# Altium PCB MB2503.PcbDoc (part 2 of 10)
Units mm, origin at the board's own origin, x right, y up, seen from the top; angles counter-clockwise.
Board outline 127 x 97 mm, 6 copper layers (Top Layer, Signal Layer 1, Signal Layer 2, Signal Layer 3, Signal Layer 4, Bottom Layer), stack 1.557 mm thick; 572 components, 468 nets, 2377 pads, 1704 vias.
Unrouted connection lines stored in the file: 3.
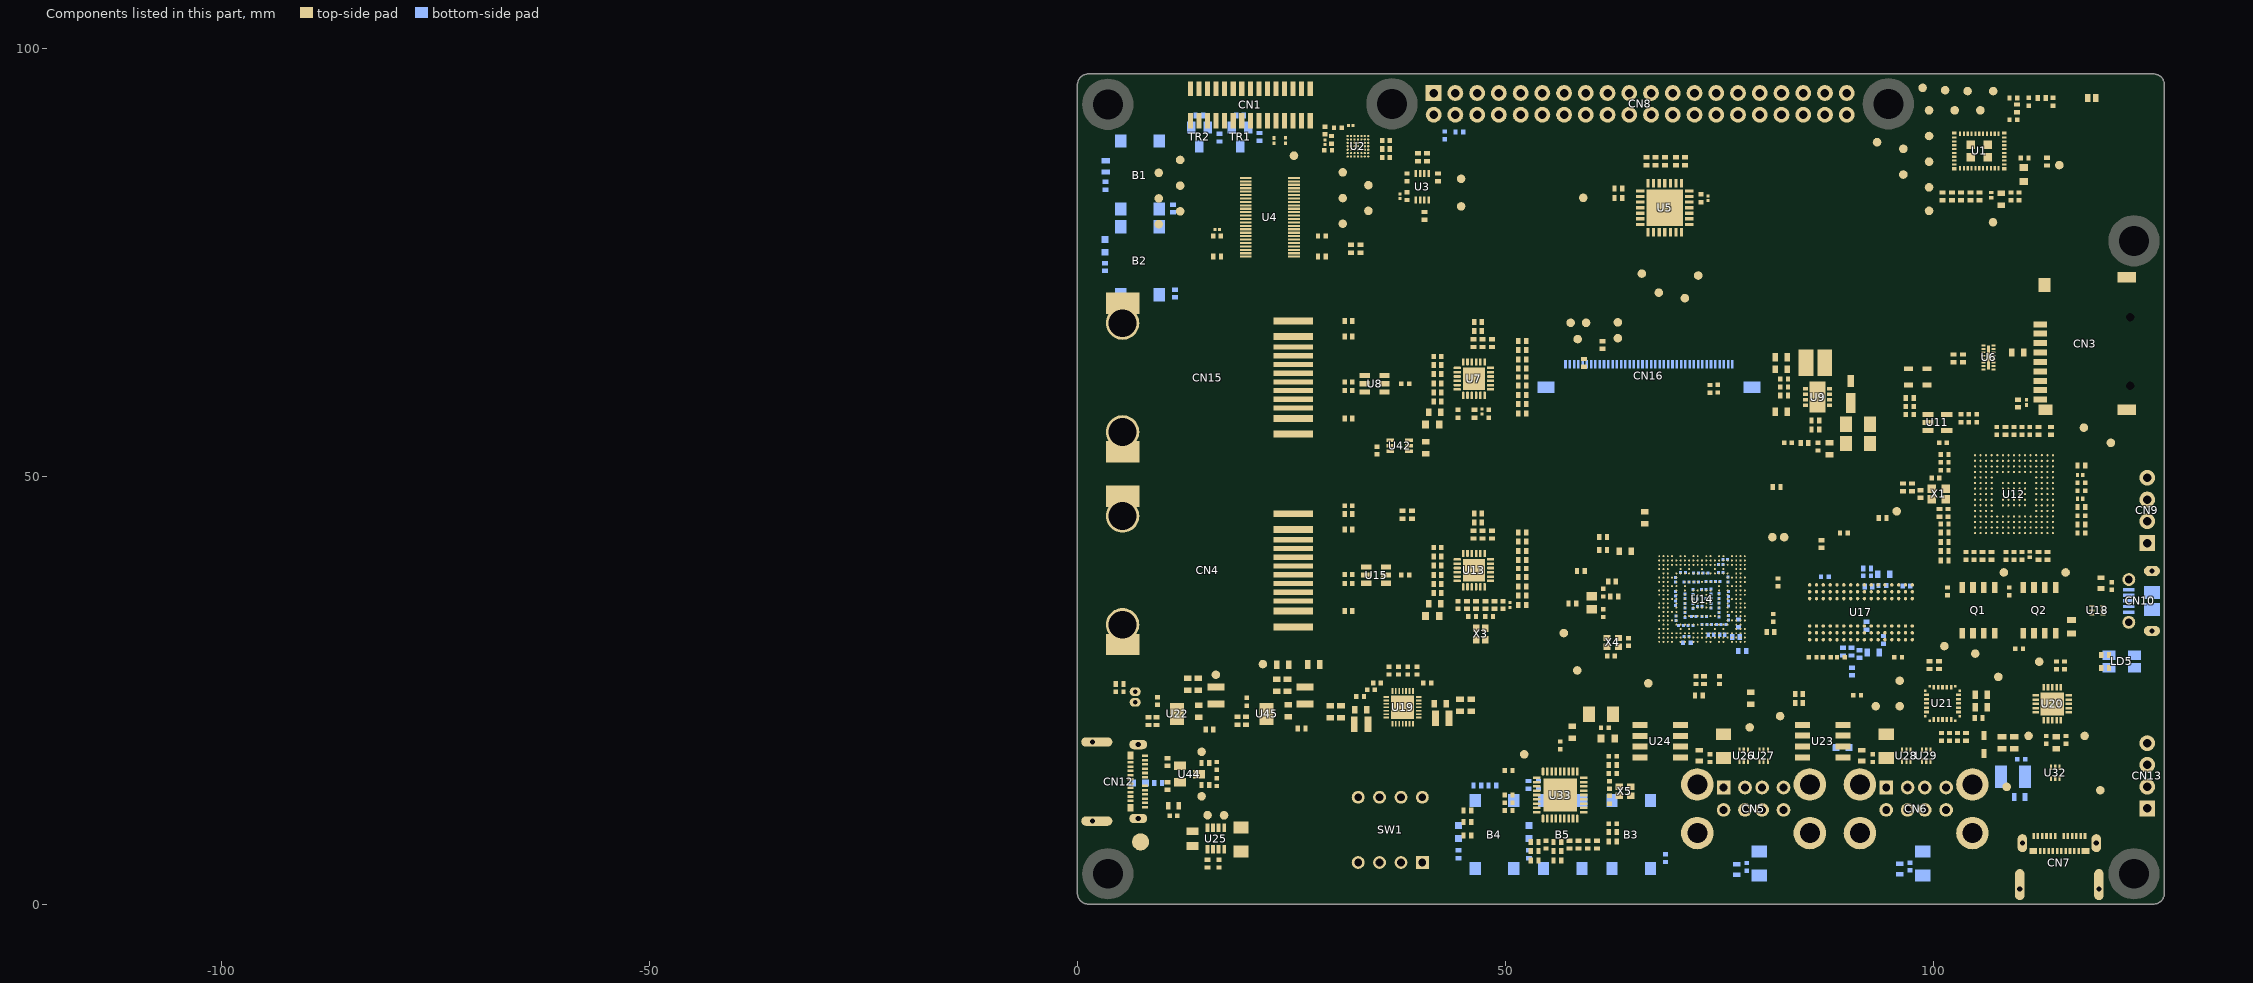
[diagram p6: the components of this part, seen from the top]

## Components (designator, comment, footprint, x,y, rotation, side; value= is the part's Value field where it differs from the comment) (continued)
TP32 "Test Point" TP_SMD_1MM#1 9.5,79.45 r90 top value=N/A
TP33 "Test Point" TP_SMD_1MM#1 72.525,73.45 r90 top value=N/A
TP34 "Test Point" TP_SMD_1MM#1 65.95,73.675 r90 top value=N/A
TP35 "Test Point" TP_SMD_1MM#1 70.975,70.8 r90 top value=N/A
TP36 "Test Point" TP_SMD_1MM#1 67.925,71.45 r90 top value=N/A
TP37 "Test Point" TP_SMD_1MM#1 59.425,67.925 r90 top value=N/A
TP38 "Test Point" TP_SMD_1MM#1 117.6,55.675 r180 top value=N/A
TP39 "Test Point" TP_SMD_1MM#1 120.75,53.9 r180 top value=N/A
TP40 "Test Point" TP_SMD_1MM#1 58.45,66.025 r90 top value=N/A
TP41 "Test Point" TP_SMD_1MM#1 63.145,66.125 r90 top value=N/A
TP42 "Test Point" TP_SMD_1MM#1 57.625,67.925 r90 top value=N/A
TP43 "Test Point" TP_SMD_1MM#1 63.145,67.975 r180 top value=N/A
TP44 "Test Point" TP_SMD_1MM#1 95.725,45.9 r270 top value=N/A
TP45 "Test Point" TP_SMD_1MM#2 81.25,42.875 r0 top value=N/A
TP46 "Test Point" TP_SMD_1MM#3 82.575,42.825 r0 top value=N/A
TP47 "Test Point" TP_SMD_1MM#1 108.25,38.75 r180 top value=N/A
TP48 "Test Point" TP_SMD_1MM#1 115.45,38.75 r180 top value=N/A
TP49 "Test Point" TP_SMD_1MM#1 21.675,28.05 r90 top value=N/A
TP50 "Test Point" TP_SMD_1MM#1 56.825,31.675 r90 top value=N/A
TP51 "Test Point" TP_SMD_1MM#1 101.3,30.15 r180 top value=N/A
TP52 "Test Point" TP_SMD_1MM#1 104.9,29.275 r180 top value=N/A
TP53 "Test Point" TP_SMD_1MM#1 112.375,28.325 r180 top value=N/A
TP54 "Test Point" TP_SMD_1MM#1 58.4,27.3 r90 top value=N/A
TP55 "Test Point" TP_SMD_1MM#1 107.6,26.55 r180 top value=N/A
TP56 "Test Point" TP_SMD_1MM#1 96.075,26.1 r180 top value=N/A
TP57 "Test Point" TP_SMD_1MM#1 66.7,25.8 r90 top value=N/A
TP58 "Test Point" TP_SMD_1MM#4 93.275,23.1 r180 top value=N/A
TP59 "Test Point" TP_SMD_1MM#1 96.075,23.125 r180 top value=N/A
TP61 "Test Point" TP_SMD_1MM#1 82.1,21.975 r90 top value=N/A
TP62 "Test Point" TP_SMD_1MM#1 16.175,26.8 r90 top value=N/A
TP63 "Test Point" TP_SMD_1MM#1 78.55,20.65 r180 top value=N/A
TP64 "Test Point" TP_SMD_1MM#1 111.125,19.65 r270 top value=N/A
TP65 "Test Point" TP_SMD_1MM#1 117.675,19.65 r270 top value=N/A
TP67 "Test Point" TP_SMD_1MM#1 17.125,10.375 r90 top value=N/A
TP68 "Test Point" TP_SMD_1MM#1 15.2,10.4 r180 top value=N/A
TP73 "Test Point" TP_SMD_1MM#1 14.5,12.6 r270 top value=N/A
TP74 "Test Point" TP_SMD_1MM#1 108.575,13.7 r180 top value=N/A
TP75 "Test Point" TP_SMD_1MM#1 119.511,13.303 r180 top value=N/A
TP76 "Test Point" TP_SMD_2MM 7.375,7.275 r180 top value=N/A
TP77 "Test Point" TP_SMD_1MM#1 14.5,17.8 r180 top value=N/A
TR1 "BSN20" MOS_SOT23 19,89.65 r0 bottom value=FDV301N
TR2 "BSN20" MOS_SOT23 14.25,89.65 r0 bottom value=FDV301N
U1 "LBEE5KL1DX-883" MOD_WLAN-BT_MURATA_LBEE5KL1DX-883 105.375,88 r180 top value=LBEE5KL1DX-977
U2 "STMIPID02" ICC_VFBGA49_3X3_P040 32.775,88.55 r270 top value=STMIPID02/TR
U3 "SN74LVC2T45DCUT" ICC_VSSOP8_DCU_R-PDSO-G8_2X2P30_P050 40.29,83.815 r0 top
U4 "SN74AVC16T245DGVR" ICC_TVSOP48_9P8X6P6_P040 22.475,80.25 r270 top
U5 "MCP23017" ICC_QFN28-EPAD_6X6_P065 68.625,81.375 r90 top value=MCP23017T-E/ML
U6 "EMIF06-MSD02N16" ESD_UQFN16L-EPAD_3P5X1P2_P040 106.45,63.875 r270 top
U7 "LAN8742A-CZ-TR" ICC_VQFN24-EPAD_4X4_P050 46.325,61.4 r90 top
U8 "USBLC6-4SC6" ESD_SOT23-6L 34.725,60.8 r270 top
U9 "STLD40DPUR" ICC_QFN8-EPAD_3X3_P065 86.475,59.25 r270 top
U10 "ESD-TRANSIL" ESD_ST0201 110.875,58.625 r270 top value=ESDALC6V1-1U2
U11 "LD3985M33R" REG_SOT23-5L 100.475,56.275 r270 top
U12 "ST-LINKV3E" ICC_UFBGA201_176+25_10X10_P065 109.425,47.9 r0 top value=STM32F723IEK6
U13 "LAN8742A-CZ-TR" ICC_VQFN24-EPAD_4X4_P050 46.325,39.025 r90 top
U14 "STM32MP135FAF7" ICC_TFBGA320_11X11_STM32MP135FA7_P050_H1P20 72.975,35.65 r0 top locked
U15 "USBLC6-4SC6" ESD_SOT23-6L 34.9,38.45 r270 top
U16 "ESD-TRANSIL" ESD_QFN2_1P6X1_P125 119.575,37.5 r90 top value=ESDA7P60-1U1M
U17 "NT5CC256M16ER-EK" ICC_VFBGA96_9x13_P080 91.55,34.1 r270 top locked
U18 "ECMF02-2AMX6" ESD_QFN-6L_1P7X1P5_P050 119.175,34.325 r270 top
U19 "STPMIC1L" ICC_VFQFPN28-EPAD_4X4_P040 38,23 r90 top value=STPMIC1LDPQR
U20 "TCPP03-M20" ICC_QFN20-EPAD_4X4_P050 113.9,23.4 r270 top
U21 "STM32G071G8U6N" ICC_UFQFPN28_4X4_P050 101.075,23.45 r0 top
U22 "ST1S31PUR" ICC_VFDFPN8-EPAD_3X3_P065 11.65,22.225 r270 top
U23 "STMPS2252MTR" ICC_SO8_5X4_P127 87.1,19.05 r270 top
U24 "STMPS2252MTR" ICC_SO8_5X4_P127 68.1,19.025 r270 top
U25 "STEF05SGR" ICC_TSOT23-8L 16.175,7.65 r0 top
U26 "ECMF02-2AMX6" ESD_QFN-6L_1P7X1P5_P050 77.85,17.35 r180 top
U27 "ECMF02-2AMX6" ESD_QFN-6L_1P7X1P5_P050 80.175,17.35 r180 top
U28 "ECMF02-2AMX6" ESD_QFN-6L_1P7X1P5_P050 96.85,17.35 r180 top
U29 "ECMF02-2AMX6" ESD_QFN-6L_1P7X1P5_P050 99.175,17.35 r180 top
U30 "ESD-TRANSIL" ESD_QFN1610_2N_1K_2A 72.65,17.35 r90 top value=ESDA7P120-1U1M
U31 "ESD-TRANSIL" ESD_QFN1610_2N_1K_2A 91.65,17.35 r90 top value=ESDA7P120-1U1M
U32 "ECMF02-2AMX6" ESD_QFN-6L_1P7X1P5_P050 114.25,15.35 r180 top
U33 "USB2514B-AEZC" ICC_QFN36-EPAD_6X6_P050 56.4,12.75 r180 top
U34 "ESD-TRANSIL" ESD_QFN1610_2N_1K_2A 11.225,11.5 r0 top value=ESDA25P35-1U1M
U35 "RK043FN78H-CT661C" LCD_DRAWING_ROCKTEK_RK043FN78H-CT661C -63.4,76.4 r180 bottom
U36 "ESD-TRANSIL" ESD_QFN1610_2N_1K_2A 110.1,12.523 r180 bottom value=ESDA25P35-1U1M
U37 "ESD-TRANSIL" ESD_ST0201 54.692,13.937 r90 bottom value=ESDALC6V1-1U2
U38 "ESD-TRANSIL" ESD_QFN1610_2N_1K_2A 96.075,4.1 r270 bottom value=ESDA7P120-1U1M
U39 "ESD-TRANSIL" ESD_QFN1610_2N_1K_2A 77.05,4.05 r270 bottom value=ESDA7P120-1U1M
U40 "ESD-TRANSIL" ESD_ST0201 24.3,89.213 r270 top value=ESDALC6V1-1U2
U41 "ESD-TRANSIL" ESD_ST0201 22.975,89.2 r270 top value=ESDALC6V1-1U2
U42 "TPS22919" ICC_SC70-6_DCK_R-PDSO-G6_2X1P25_P065 37.65,53.55 r270 top value=TPS22919DCKR
U44 "ESDA25L" ESD_SOT23 13.075,15.2 r270 top
U45 "ST1S31PUR" ICC_VFDFPN8-EPAD_3X3_P065 22.1,22.225 r270 top
X1 "OSCILLATOR_4_PINS" OSC_NDK_NZ2520SB_4P 100.625,47.925 r0 top value=25MHz
X2 "XTAL_2_PINS" CRY_NX2012SA_2P 60.075,35.2 r270 top value=32.768KHz
X3 "XTAL_4_PINS" CRY_NX2016SA_4P 47.1,31.575 r90 top value=25MHz
X4 "XTAL_4_PINS" CRY_NX2016SA_4P 62.55,30.575 r0 top value=24MHz
X5 "XTAL_4_PINS" CRY_NX2016SA_4P 63.975,13.175 r180 top value=24MHz

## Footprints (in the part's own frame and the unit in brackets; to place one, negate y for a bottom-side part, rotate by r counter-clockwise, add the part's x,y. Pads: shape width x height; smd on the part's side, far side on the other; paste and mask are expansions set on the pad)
C0201_H0P5 [mm] "MCD-01534"
  rect 0.4x0.5 smd mask+0.05: 1(-0.3,0) 2(0.3,0)
  Top Layer keep-out region: -0.099,-0.25 0.101,-0.25 0.101,0.25 -0.099,0.25
  body extent -0.35,-0.2 0.35,0.2, height 0.55
C0201_MURATA_GRM033_H0P3 [mm] "GRM033R60J105ME11"
  rect 0.35x0.35 smd mask+0.05: 1(-0.275,0) 2(0.275,0)
  Top Layer keep-out region: -0.1,-0.175 0.1,-0.175 0.1,0.175 -0.1,0.175
  body extent -0.32,-0.17 0.32,0.17, height 0.33
C0402#1 [mm]
  rect 0.51x0.56 smd mask+0.05: 1(-0.45,0) 2(0.45,0)
  Top Layer keep-out region: -0.175,-0.275 0.175,-0.275 0.175,0.275 -0.175,0.275
  body extent -0.5,-0.3 0.5,0.3, height 0.4
C0402#2 [mm]
  rect 0.51x0.56 smd mask+0.05: 1(-0.45,0) 2(0.45,0)
  body extent -0.5,-0.3 0.5,0.3, height 0.4
C0603#1 [mm]
  rect 0.64x0.89 smd mask+0.05: 1(-0.7,0) 2(0.7,0)
  Top Layer keep-out region: -0.375,-0.45 0.375,-0.45 0.375,0.45 -0.375,0.45
  body extent -0.9,-0.5 0.9,0.5, height 1.4
C0603#2 [mm]
  rect 0.64x0.89 smd mask+0.05: 1(-0.7,0) 2(0.7,0)
  silkscreen extent -1.05,-0.55 1.02,0.55, body extent -0.9,-0.5 0.9,0.5, height 1.4
C0805 [mm]
  rect 0.9x1.4 smd mask+0.05: 1(-0.85,0) 2(0.85,0)
  silkscreen extent -1.3,-0.77 1.3,0.77, body extent -1.1,-0.7 1.1,0.7, height 1.35
C1206_H1P6 [mm]
  rect 1.4x1.78 smd mask+0.05: 1(-1.4,0) 2(1.4,0)
  silkscreen extent -2.12,-0.97 2.15,0.97, body extent -1.7,-0.9 1.7,0.9, height 1.8
C1206_H1P25 [mm]
  rect 1.4x1.78 smd mask+0.05: 1(-1.4,0) 2(1.4,0)
  silkscreen extent -2.12,-0.97 2.15,0.97, body extent -1.7,-0.9 1.7,0.9, height 1.45
C1210 [mm]
  rect 1.4x2.6 smd mask+0.05: 1(-1.4,0) 2(1.4,0)
  silkscreen extent -2.1,-1.43 2.1,1.43, body extent -1.75,-1.35 1.75,1.35, height 2.5
CON_DUAL-USB-TYPE-A_CONEXCON_5600-3081 [mm]
  round 1.6 hole 0.92: B1(-3.5,13.01) B2(-1,13.01) B3(1,13.01) B4(3.5,13.01) T2(-1,15.63) T3(1,15.63) T4(3.5,15.63)
  round 3.8 hole 2.33: CH1(6.57,10.3) CH2(-6.57,10.3) CH3(-6.57,15.98) CH4(6.57,15.98)
  rect 1.6x1.6 hole 0.92: T1(-3.5,15.63)
  silkscreen extent -7.3,-0.4 7.3,17.85, body extent -7.83,-0.6 7.87,17.85, height 16.2
CON_MICROSD_ATOM_MR01A-01211 [mm]
  rect 0.7x1.6 smd paste+0 mask+0.05: 1(2.25,14.5) 2(1.15,14.5) 3(0.05,14.5) 4(-1.05,14.5) 5(-2.15,14.5) 6(-3.25,14.5) 7(-4.35,14.5) 8(-5.45,14.5) 9(-6.55,14.5)
  rect 1.2x1.6 smd paste+0 mask+0.05: 10(-7.75,13.9)
  rect 1.2x2.2 smd paste+0 mask+0.05: 11(-7.75,4.4) 12(7.75,4.4)
  rect 1.6x1.4 smd paste+0 mask+0.05: 13(6.85,14)
  round 0.5 hole 1 unplated paste-2539.97 mask+0.05: NPTH1(-4.95,4) NPTH2(3.05,4)
  Top Layer pour cut-out: -6.1,10.1 2.9,10.1 2.9,8.1 -6.1,8.1
  Top Layer pour cut-out: -8.35,8.1 -8.35,12.9 -6.9,12.9 -6.9,8.1
  Top Layer keep-out region: -6.1,10.1 2.9,10.1 2.9,8.1 -6.1,8.1
  Top Layer keep-out region: -8.35,8.1 -8.35,12.9 -6.9,12.9 -6.9,8.1
  silkscreen extent -7.35,-5.3 7.35,14.5, body extent -8.05,0 8.05,15, height 1.9
CON_MOLEX_53047-0210 [mm]
  oval 1x1.3 hole 0.5 mask+0.05: 1(-0.625,0) 2(0.625,0)
  silkscreen extent -2.12,-1.15 2.13,2.05, body extent -2.12,-1.15 2.13,2.05, height 4.2
CON_MOLEX_5051104091 [mm] "MCD-02589"
  rect 0.3x1 smd mask+0.05: 1(-9.75,1.1) 2(-9.25,1.1) 3(-8.75,1.1) 4(-8.25,1.1) 5(-7.75,1.1) 6(-7.25,1.1) 7(-6.75,1.1) 8(-6.25,1.1) 9(-5.75,1.1) 10(-5.25,1.1) 11(-4.75,1.1) 12(-4.25,1.1) 13(-3.75,1.1) 14(-3.25,1.1) 15(-2.75,1.1) 16(-2.25,1.1) 17(-1.75,1.1) 18(-1.25,1.1) 19(-0.75,1.1) 20(-0.25,1.1) 21(0.25,1.1) 22(0.75,1.1) 23(1.25,1.1) 24(1.75,1.1) 25(2.25,1.1) 26(2.75,1.1) 27(3.25,1.1) 28(3.75,1.1) 29(4.25,1.1) 30(4.75,1.1) 31(5.25,1.1) 32(5.75,1.1) 33(6.25,1.1) 34(6.75,1.1) 35(7.25,1.1) 36(7.75,1.1) 37(8.25,1.1) 38(8.75,1.1) 39(9.25,1.1) 40(9.75,1.1)
  rect 2x1.3 smd mask+0.05: MT1(-12.05,-1.6) MT2(12.05,-1.6)
  silkscreen extent -12.35,-4 12.35,1.25, body extent -12.75,-4 12.75,1.3, height 1.88
CON_RJ45_PHC_RMT-119A-12F6-GY-02 [mm] "MCD-02475"
  rect 0.81x4.6 smd mask+0.05: 1(6.61,25.2) 2(4.77,25.2) 11(-4.77,25.2) 12(-6.61,25.2)
  rect 0.61x4.6 smd mask+0.05: 3(3.57,25.2) 4(2.55,25.2) 5(1.53,25.2) 6(0.51,25.2) 7(-0.51,25.2) 8(-1.53,25.2) 9(-2.55,25.2) 10(-3.57,25.2)
  rect 2.5x3.9 smd mask+0.05: 13(-8.67,5.28) 14(8.67,5.28)
  round 3.9 hole 3.25 mask+0.05: 13(-6.35,5.28) 14(6.35,5.28)
  silkscreen extent -8.9,-0.01 8.9,25.65, body extent -9.5,0 9.5,25.65, height 13.61
CON_SAMTEC_TSW-104-07-G-S [mm]
  rect 1.85x1.85 / inner round 1.85 / far side rect 1.85x1.85 hole 1 mask+0.05: 1(-3.81,0)
  round 1.85 hole 1 mask+0.05: 2(-1.27,0) 3(1.27,0) 4(3.81,0)
  silkscreen extent -5.12,-1.3 5.12,1.3, body extent -5.21,-1.37 5.18,1.37, height 8.38
CON_SAMTEC_TSW-120-07-G-D [mm]
  rect 1.85x1.85 / inner round 1.85 / far side rect 1.85x1.85 hole 1 mask+0.05: 1(-24.13,-1.27)
  round 1.85 hole 1 mask+0.05: 2(-24.13,1.27) 3(-21.59,-1.27) 4(-21.59,1.27) 5(-19.05,-1.27) 6(-19.05,1.27) 7(-16.51,-1.27) 8(-16.51,1.27) 9(-13.97,-1.27) 10(-13.97,1.27) 11(-11.43,-1.27) 12(-11.43,1.27) 13(-8.89,-1.27) 14(-8.89,1.27) 15(-6.35,-1.27) 16(-6.35,1.27) 17(-3.81,-1.27) 18(-3.81,1.27) 19(-1.27,-1.27) 20(-1.27,1.27) 21(1.27,-1.27) 22(1.27,1.27) 23(3.81,-1.27) 24(3.81,1.27) 25(6.35,-1.27) 26(6.35,1.27) 27(8.89,-1.27) 28(8.89,1.27) 29(11.43,-1.27) 30(11.43,1.27) 31(13.97,-1.27) 32(13.97,1.27) 33(16.51,-1.27) 34(16.51,1.27) 35(19.05,-1.27) 36(19.05,1.27) 37(21.59,-1.27) 38(21.59,1.27) 39(24.13,-1.27) 40(24.13,1.27)
  silkscreen extent -25.4,-2.54 25.4,2.54, body extent -25.4,-2.55 25.4,2.54, height 8.38
CON_TE-CONNECTIVITY_1-1734248-5 [mm] "MCD-02225"
  rect 0.6x1.85 smd mask+0.05: 1(7,1.875) 2(6,1.875) 3(5,1.875) 4(4,1.875) 5(3,1.875) 6(2,1.875) 7(1,1.875) 8(0,1.875) 9(-1,1.875) 10(-2,1.875) 11(-3,1.875) 12(-4,1.875) 13(-5,1.875) 14(-6,1.875) 15(-7,1.875)
  rect 0.6x1.65 smd mask+0.05: 16(7,-1.875) 17(6,-1.875) 18(5,-1.875) 19(4,-1.875) 20(3,-1.875) 21(2,-1.875) 22(1,-1.875) 23(0,-1.875) 24(-1,-1.875) 25(-2,-1.875) 26(-3,-1.875) 27(-4,-1.875) 28(-5,-1.875) 29(-6,-1.875) 30(-7,-1.875)
  silkscreen extent -11.2,-2.85 11.2,1.85, body extent -11.2,-2.7 11.2,2.4, height 7.7
CON_USB-TYPEC_MOLEX_2012670005 [mm] "MCD-02421"
  rect 0.3x0.7 smd mask+0.05: A1(-3,3.085) A2(-2.5,3.085) A3(-2,3.085) A4(-1.5,3.085) A5(-1,3.085) A6(-0.5,3.085) A7(0.5,3.085) A8(1,3.085) A9(1.5,3.085) A10(2,3.085) A11(2.5,3.085) A12(3,3.085) B2(2.25,1.385) B3(1.75,1.385) B4(1.25,1.385) B5(0.75,1.385) B6(0.25,1.385) B7(-0.25,1.385) B8(-0.75,1.385) B9(-1.25,1.385) B10(-1.75,1.385) B11(-2.25,1.385)
  rect 0.9x0.7 smd mask+0.05: B1(3.05,1.385) B12(-3.05,1.385)
  oval 1.1x2.1 hole 0.6 slot 1.6 at 90 deg mask+0.05: SH1(-4.32,2.275) SH2(4.32,2.275)
  oval 1.1x2.6 hole 0.6 slot 2.1 at 90 deg mask+0.05: SH3(-4.62,-3.085) SH4(4.62,-3.085)
  oval 1.1x3.6 all layers, no hole mask+0.05: SH3(-4.62,-2.55) SH4(4.62,-2.55)
  silkscreen extent -4.7,-5.02 4.7,1.1, body extent -4.7,-5.03 4.69,3.27, height 3.67
CON_USBMICROB_MOLEX_105017-0001_H2P90 [mm]
  rect 0.4x1.35 smd mask+0.05: 1(-1.3,4.15) 2(-0.65,4.15) 3(0,4.15) 4(0.65,4.15) 5(1.3,4.15)
  round 1.5 hole 0.9 mask+0.05: 6(-2.5,4.15) 7(2.5,4.15)
  oval 1.2x1.9 hole 0.6 slot 1.3 at 90 deg mask+0.05: 8(3.5,1.45) 9(-3.5,1.45)
  rect 1.5x1.9 smd mask+0.05: 10(-1,1.45) 11(1,1.45)
  Top Layer region: 2.3,2.4 3.5,2.4 3.5,0.5 2.3,0.5 2.3,2.4
  Top Layer region: -3.5,2.4 -2.3,2.4 -2.3,0.5 -3.5,0.5 -3.5,2.4
  silkscreen extent -4,-0.7 4,4.6, body extent -4.1,-1.15 4.1,4.66, height 2.9
CRY_NX2012SA_2P [mm]
  rect 1x1.25 smd mask+0.05: 1(-0.75,0) 2(0.75,0)
  silkscreen extent -1.05,-0.75 1.05,0.75, body extent -1.05,-0.63 1.05,0.63, height 0.6
CRY_NX2016SA_4P [mm]
  rect 0.85x0.75 smd mask+0.05: 1(-0.675,-0.525) 2(0.675,-0.525) 3(0.675,0.525) 4(-0.675,0.525)
  silkscreen extent -1.22,-1.02 1.05,0.85, body extent -1.05,-0.85 1.05,0.85, height 0.7
DIO_DO216-AA [mm]
  rect 1.38x0.75 smd mask+0.05: 1(1.515,0)
  rect 2.32x1.1 smd mask+0.05: 2(-1.045,0)
  Top Layer region: -1.705,-1.015 0.115,-1.015 0.115,1.015 -1.705,1.015
  silkscreen extent -2.25,-1.22 0.72,1.22, body extent -2.02,-1.02 1.83,1.02, height 1.15
DIO_SOD323 [mm]
  rect 1.06x0.54 smd mask+0.05: 1(-1.07,0) 2(1.07,0)
  silkscreen extent -0.9,-0.72 0.9,0.72, body extent -1.3,-0.78 1.3,0.78, height 1.17
ESD_QFN2_1P6X1_P125 [mm]
  rect 0.55x0.8 smd mask+0.05: 1(-0.625,0) 2(0.625,0)
  silkscreen extent -1,-0.55 0.85,0.55, body extent -0.85,-0.55 0.85,0.55, height 0.61
ESD_QFN1610_2N_1K_2A [mm] "DFN, 2-Leads, Body 1.60x1.00mm"
  rect 0.55x0.9 smd mask+0.05: 1(-0.625,0) 2(0.625,0)
  silkscreen extent -1.02,-0.58 0.85,0.58, body extent -0.85,-0.55 0.85,0.55, height 0.6
ESD_QFN-6L_1P7X1P5_P050 [mm]
  rect 0.25x0.6 smd mask+0.05: 1(-0.5,-0.65) 2(0,-0.65) 3(0.5,-0.65) 4(0.5,0.65) 5(0,0.65) 6(-0.5,0.65)
  body extent -0.9,-0.8 0.9,0.8, height 0.56
ESD_SOT23 [mm]
  rect 1x1.4 smd mask+0.05: 1(-0.95,-1.1) 2(0.95,-1.1) 3(0,1.1)
  silkscreen extent -1.63,-0.82 1.63,0.82, body extent -1.56,-1.5 1.56,1.5, height 1.4
ESD_SOT23-6L [mm]
  rect 0.6x1.2 smd mask+0.05: 1(-0.95,-1.15) 2(0,-1.15) 3(0.95,-1.15) 4(0.95,1.15) 5(0,1.15) 6(-0.95,1.15)
  silkscreen extent -1.53,-0.87 1.53,0.87, body extent -1.52,-1.5 1.52,1.5, height 1.45
ESD_ST0201 [mm]
  rect 0.425x0.33 smd mask+0.05: 1(-0.312,0) 2(0.312,0)
  silkscreen extent -0.55,-0.3 0.33,0.3, body extent -0.34,-0.18 0.34,0.18, height 0.34
ESD_UQFN16L-EPAD_3P5X1P2_P040 [mm]
  rect 0.2x0.45 smd mask+0.05: 1(-1.4,-0.575) 2(-1,-0.575) 3(-0.6,-0.575) 4(-0.2,-0.575) 5(0.2,-0.575) 6(0.6,-0.575) 7(1,-0.575) 8(1.4,-0.575) 9(1.4,0.575) 10(1,0.575) 11(0.6,0.575) 12(0.2,0.575) 13(-0.2,0.575) 14(-0.6,0.575) 15(-1,0.575) 16(-1.4,0.575)
  rect 2.8x0.3 smd mask+0.05: EP(0,0)
  body extent -1.78,-0.63 1.78,0.63, height 0.56
FIL_0603_H0P65 [mm]
  rect 0.8x0.95 smd mask+0.05: 1(-0.8,0) 2(0.8,0)
  silkscreen extent -1.33,-0.6 1.33,0.6, body extent -0.87,-0.47 0.87,0.47, height 0.65
ICC_QFN8-EPAD_3X3_P065 [mm]
  rect 0.4x0.6 smd paste+0 mask+0.05: 1(-0.975,-1.4) 2(-0.325,-1.4) 3(0.325,-1.4) 4(0.975,-1.4) 5(0.975,1.4) 6(0.325,1.4) 7(-0.325,1.4) 8(-0.975,1.4)
  rect 3.6x1.9 smd paste+0 mask+0: 9(0,0)
  body extent -1.58,-1.58 1.58,1.58, height 1
ICC_QFN20-EPAD_4X4_P050 [mm] "MCD-02130"
  rect 0.75x0.3 smd mask+0.05: 1(-1.925,1) 2(-1.925,0.5) 3(-1.925,0) 4(-1.925,-0.5) 5(-1.925,-1) 11(1.925,-1) 12(1.925,-0.5) 13(1.925,0) 14(1.925,0.5) 15(1.925,1)
  rect 0.3x0.75 smd mask+0.05: 6(-1,-1.925) 7(-0.5,-1.925) 8(0,-1.925) 9(0.5,-1.925) 10(1,-1.925) 16(1,1.925) 17(0.5,1.925) 18(0,1.925) 19(-0.5,1.925) 20(-1,1.925)
  rect 2.7x2.7 smd mask+0.05: 21(0,0)
  body extent -2.13,-2.13 2.13,2.13, height 1.01
ICC_QFN28-EPAD_6X6_P065 [mm] "MCD-02210"
  rect 0.37x1 smd mask+0.05: 1(-1.95,-2.85) 2(-1.3,-2.85) 3(-0.65,-2.85) 4(0,-2.85) 5(0.65,-2.85) 6(1.3,-2.85) 7(1.95,-2.85) 15(1.95,2.85) 16(1.3,2.85) 17(0.65,2.85) 18(0,2.85) 19(-0.65,2.85) 20(-1.3,2.85) 21(-1.95,2.85)
  rect 1x0.37 smd mask+0.05: 8(2.85,-1.95) 9(2.85,-1.3) 10(2.85,-0.65) 11(2.85,0) 12(2.85,0.65) 13(2.85,1.3) 14(2.85,1.95) 22(-2.85,1.95) 23(-2.85,1.3) 24(-2.85,0.65) 25(-2.85,0) 26(-2.85,-0.65) 27(-2.85,-1.3) 28(-2.85,-1.95)
  rect 4.25x4.25 smd mask+0.05: 29(0,0)
  body extent -3.05,-3.05 3.05,3.05, height 1
ICC_QFN36-EPAD_6X6_P050 [mm]
  rrect50% 0.3x0.9 smd mask+0.05: 1(-2,-2.75) 9(2,-2.75) 19(2,2.75) 27(-2,2.75)
  rect 0.3x0.9 smd mask+0.05: 2(-1.5,-2.75) 3(-1,-2.75) 4(-0.5,-2.75) 5(0,-2.75) 6(0.5,-2.75) 7(1,-2.75) 8(1.5,-2.75) 20(1.5,2.75) 21(1,2.75) 22(0.5,2.75) 23(0,2.75) 24(-0.5,2.75) 25(-1,2.75) 26(-1.5,2.75)
  rrect50% 0.9x0.3 smd mask+0.05: 10(2.75,-2) 18(2.75,2) 28(-2.75,2) 36(-2.75,-2)
  rect 0.9x0.3 smd mask+0.05: 11(2.75,-1.5) 12(2.75,-1) 13(2.75,-0.5) 14(2.75,0) 15(2.75,0.5) 16(2.75,1) 17(2.75,1.5) 29(-2.75,1.5) 30(-2.75,1) 31(-2.75,0.5) 32(-2.75,0) 33(-2.75,-0.5) 34(-2.75,-1) 35(-2.75,-1.5)
  rect 3.9x3.9 smd mask+0.05: 37(0,0)
  body extent -3.06,-3.06 3.06,3.06, height 1
ICC_SC70-6_DCK_R-PDSO-G6_2X1P25_P065 [mm]
  rect 0.4x0.9 smd mask+0.05: 1(-0.65,-1.1) 2(0,-1.1) 3(0.65,-1.1) 4(0.65,1.1) 5(0,1.1) 6(-0.65,1.1)
  silkscreen extent -1.22,-1.38 1.1,0.7, body extent -1.1,-1.05 1.1,1.05, height 1.11
ICC_SO8_5X4_P127 [mm]
  rect 0.7x1.75 smd mask+0.05: 1(-1.905,-2.375) 2(-0.635,-2.375) 3(0.635,-2.375) 4(1.905,-2.375) 5(1.905,2.375) 6(0.635,2.375) 7(-0.635,2.375) 8(-1.905,2.375)
  silkscreen extent -2.73,-3.25 2.58,2, body extent -2.57,-3 2.57,3, height 1.75
ICC_TFBGA320_11X11_STM32MP135FA7_P050_H1P20 [mm] "MCD-02251"
  round 0.23 smd paste+0.025 mask+0.05: A1(-5,5) A2(-4.5,5) A3(-4,5) A4(-3.5,5) A6(-2.5,5) A7(-2,5) A9(-1,5) A10(-0.5,5) A12(0.5,5) A13(1,5) A15(2,5) A16(2.5,5) A18(3.5,5) A19(4,5) A20(4.5,5) A21(5,5) AA1(-5,-5) AA2(-4.5,-5) AA3(-4,-5) AA4(-3.5,-5) AA6(-2.5,-5) AA7(-2,-5) AA9(-1,-5) AA10(-0.5,-5) AA12(0.5,-5) AA13(1,-5) AA15(2,-5) AA16(2.499,-5) AA18(3.499,-5) AA19(3.999,-5) AA20(4.499,-5) AA21(4.999,-5) B1(-5,4.5) B2(-4.5,4.5) B3(-4,4.5) B4(-3.5,4.5) B5(-3,4.5) B6(-2.5,4.5) B7(-2,4.5) B8(-1.5,4.5) B9(-1,4.5) B10(-0.5,4.5) B11(0,4.5) B12(0.5,4.5) B13(1,4.5) B14(1.5,4.5) B15(2,4.5) B16(2.5,4.5) B17(3,4.5) B18(3.5,4.5) B19(4,4.5) B20(4.5,4.5) B21(5,4.5) C1(-5,4) C2(-4.5,4) C3(-4,4) C4(-3.5,4) C5(-3,4) C6(-2.5,4) C7(-2,4) C8(-1.5,4) C9(-1,4) C10(-0.5,4) C11(0,4) C12(0.5,4) C13(1,4) C14(1.5,4) C15(2,4) C16(2.5,4) C17(3,4) C18(3.5,4) C19(4,4) C20(4.5,4) C21(5,4) D1(-5,3.5) D2(-4.5,3.5) D3(-4,3.5) D6(-2.5,3.5) D8(-1.5,3.5) D11(0,3.5) D14(1.5,3.5) D16(2.5,3.5) D19(4,3.5) D20(4.5,3.5) D21(5,3.5) E2(-4.5,3) E3(-4,3) E5(-3,3) E6(-2.5,3) E7(-2,3) E8(-1.5,3) E9(-1,3) E10(-0.5,3) E11(0,3) E12(0.5,3) E13(1,3) E14(1.5,3) E15(2,3) E16(2.5,3) E17(3,3) E19(4,3) E20(4.5,3) F1(-5,2.5) F2(-4.5,2.5) F3(-4,2.5) F4(-3.5,2.5) F5(-3,2.5) F17(3,2.5) F18(3.5,2.5) F19(4,2.5) F20(4.5,2.5) F21(5,2.5) G1(-5,2) G2(-4.5,2) G3(-4,2) G5(-3,2) G7(-2,2) G8(-1.5,2) G9(-1,2) G10(-0.5,2) G11(0,2) G12(0.5,2) G13(1,2) G14(1.5,2) G15(2,2) G17(3,2) G19(4,2) G20(4.5,2) G21(5,2) H2(-4.5,1.5) H3(-4,1.5) H4(-3.5,1.5) H5(-3,1.5) H7(-2,1.5) H15(2,1.5) H17(3,1.5) H18(3.5,1.5) H19(4,1.5) H20(4.5,1.5) J1(-5,1) J2(-4.5,1) J3(-4,1) J5(-3,1) J7(-2,1) J9(-1,1) J10(-0.5,1) J11(0,1) J12(0.5,1) J13(1,1) J15(1.999,1) J17(2.999,1) J19(3.999,1) J20(4.499,1) J21(4.999,1) K1(-5,0.5) K2(-4.5,0.5) K3(-4,0.5) K5(-3,0.5) K7(-2,0.5) K9(-1,0.5) K10(-0.5,0.5) K11(0,0.5) K12(0.5,0.5) K13(1,0.5) K15(2,0.5) K17(2.999,0.5) K19(3.999,0.5) K20(4.499,0.5) K21(4.999,0.5) L2(-4.5,0) L3(-4,0) L4(-3.5,0) L5(-3,0) L7(-2,0) L9(-1,0) L10(-0.5,0) L12(0.5,0) L13(1,0) L15(2,0) L17(2.999,0) L18(3.499,0) L19(3.999,0) L20(4.499,0) M1(-5,-0.5) M2(-4.5,-0.5) M3(-4,-0.5) M5(-3,-0.5) M7(-2,-0.5) M9(-1,-0.5) M10(-0.5,-0.5) M11(0,-0.5) M12(0.5,-0.5) M13(1,-0.5) M15(2,-0.5) M17(3,-0.5) M19(4,-0.5) M20(4.5,-0.5) M21(4.999,-0.501) N1(-5,-1) N2(-4.5,-1) N3(-4,-1) N5(-3,-1) N7(-2,-1) N9(-1,-1) N10(-0.5,-1) N11(0,-1) N12(0.5,-1) N13(1,-1) N15(2,-1) N17(3,-1) N19(4,-1) N20(4.5,-1) N21(5,-1) P2(-4.5,-1.5) P3(-4,-1.5) P4(-3.5,-1.5) P5(-3,-1.5) P7(-2,-1.5) P15(2,-1.5) P17(3,-1.5) P18(3.5,-1.5) P19(4,-1.5) P20(4.5,-1.5) R1(-5,-2) R2(-4.5,-2) R3(-4,-2) R5(-3,-2) R7(-2,-2) R8(-1.5,-2) R9(-1,-2) R10(-0.5,-2) R11(0,-2) R12(0.5,-2) R13(1,-2) R14(1.5,-2) R15(2,-2) R17(2.999,-2) R19(3.999,-2) R20(4.499,-2) R21(4.999,-2) T1(-5,-2.5) T2(-4.5,-2.5) T3(-4,-2.5) T4(-3.5,-2.5) T5(-3,-2.5) T17(2.999,-2.5) T18(3.499,-2.5) T19(3.999,-2.5) T20(4.499,-2.5) T21(4.999,-2.5) U2(-4.5,-3) U3(-4,-3) U5(-3,-3) U6(-2.5,-3) U7(-2,-3) U8(-1.5,-3) U9(-1,-3) U10(-0.5,-3) U11(0,-3) U12(0.5,-3) U13(1,-3) U14(1.5,-3) U15(1.999,-3) U16(2.499,-3) U17(2.999,-3) U19(3.999,-3) U20(4.499,-3) V1(-5,-3.5) V2(-4.5,-3.5) V3(-4,-3.5) V6(-2.5,-3.5) V8(-1.5,-3.5) V11(-0.001,-3.5) V14(1.499,-3.5) V16(2.499,-3.5) V19(3.999,-3.5) V20(4.499,-3.5) V21(4.999,-3.5) W1(-5,-4) W2(-4.5,-4) W3(-4,-4) W4(-3.5,-4) W5(-3,-4) W6(-2.5,-4) W7(-2,-4) W8(-1.5,-4) W9(-1,-4) W10(-0.5,-4) W11(0,-4) W12(0.5,-4) W13(1,-4) W14(1.5,-4) W15(1.999,-4) W16(2.499,-4) W17(2.999,-4) W18(3.499,-4) W19(3.999,-4) W20(4.499,-4) W21(4.999,-4) Y1(-5,-4.5) Y2(-4.5,-4.5) Y3(-4,-4.5) Y4(-3.5,-4.5) Y5(-3,-4.5) Y6(-2.5,-4.5) Y7(-2,-4.5) Y8(-1.5,-4.5) Y9(-1,-4.5) Y10(-0.5,-4.5) Y11(0,-4.5) Y12(0.5,-4.5) Y13(1,-4.5) Y14(1.5,-4.5) Y15(1.999,-4.5) Y16(2.499,-4.5) Y17(2.999,-4.5) Y18(3.499,-4.5) Y19(3.999,-4.5) Y20(4.499,-4.5) Y21(4.999,-4.5)
  silkscreen extent -5.8,-5.5 5.5,5.8, body extent -5.5,-5.52 5.5,5.52, height 1.11
ICC_TSOT23-8L [mm]
  rect 0.45x1 smd mask+0.05: 1(-0.975,-1.25) 2(-0.325,-1.25) 3(0.325,-1.25) 4(0.975,-1.25) 5(0.975,1.25) 6(0.325,1.25) 7(-0.325,1.25) 8(-0.975,1.25)
  silkscreen extent -1.68,-1.75 1.53,0.87, body extent -1.45,-1.48 1.45,1.48, height 1.1
ICC_TVSOP48_9P8X6P6_P040 [mm] "MCD-02226"
  rect 0.25x1.35 smd mask+0.038: 1(-4.6,-2.825) 2(-4.2,-2.825) 3(-3.8,-2.825) 4(-3.4,-2.825) 5(-3,-2.825) 6(-2.6,-2.825) 7(-2.2,-2.825) 8(-1.8,-2.825) 9(-1.4,-2.825) 10(-1,-2.825) 11(-0.6,-2.825) 12(-0.2,-2.825) 13(0.2,-2.825) 14(0.6,-2.825) 15(1,-2.825) 16(1.4,-2.825) 17(1.8,-2.825) 18(2.2,-2.825) 19(2.6,-2.825) 20(3,-2.825) 21(3.4,-2.825) 22(3.8,-2.825) 23(4.2,-2.825) 24(4.6,-2.825) 25(4.6,2.825) 26(4.2,2.825) 27(3.8,2.825) 28(3.4,2.825) 29(3,2.825) 30(2.6,2.825) 31(2.2,2.825) 32(1.8,2.825) 33(1.4,2.825) 34(1,2.825) 35(0.6,2.825) 36(0.2,2.825) 37(-0.2,2.825) 38(-0.6,2.825) 39(-1,2.825) 40(-1.4,2.825) 41(-1.8,2.825) 42(-2.2,2.825) 43(-2.6,2.825) 44(-3,2.825) 45(-3.4,2.825) 46(-3.8,2.825) 47(-4.2,2.825) 48(-4.6,2.825)
  silkscreen extent -4.9,-1.9 4.9,1.9, body extent -4.9,-3.2 4.9,3.2, height 1.2
ICC_UFBGA201_176+25_10X10_P065 [mm] "IPC"
  round 0.25 smd mask+0.05: A1(-4.55,4.55) A2(-3.9,4.55) A3(-3.25,4.55) A4(-2.6,4.55) A5(-1.95,4.55) A6(-1.3,4.55) A7(-0.65,4.55) A8(0,4.55) A9(0.65,4.55) A10(1.3,4.55) A11(1.95,4.55) A12(2.6,4.55) A13(3.25,4.55) A14(3.9,4.55) A15(4.55,4.55) B1(-4.55,3.9) B2(-3.9,3.9) B3(-3.25,3.9) B4(-2.6,3.9) B5(-1.95,3.9) B6(-1.3,3.9) B7(-0.65,3.9) B8(0,3.9) B9(0.65,3.9) B10(1.3,3.9) B11(1.95,3.9) B12(2.6,3.9) B13(3.25,3.9) B14(3.9,3.9) B15(4.55,3.9) C1(-4.55,3.25) C2(-3.9,3.25) C3(-3.25,3.25) C4(-2.6,3.25) C5(-1.95,3.25) C6(-1.3,3.25) C7(-0.65,3.25) C8(0,3.25) C9(0.65,3.25) C10(1.3,3.25) C11(1.95,3.25) C12(2.6,3.25) C13(3.25,3.25) C14(3.9,3.25) C15(4.55,3.25) D1(-4.55,2.6) D2(-3.9,2.6) D3(-3.25,2.6) D4(-2.6,2.6) D5(-1.95,2.6) D6(-1.3,2.6) D7(-0.65,2.6) D8(0,2.6) D9(0.65,2.6) D10(1.3,2.6) D11(1.95,2.6) D12(2.6,2.6) D13(3.25,2.6) D14(3.9,2.6) D15(4.55,2.6) E1(-4.55,1.95) E2(-3.9,1.95) E3(-3.25,1.95) E4(-2.6,1.95) E12(2.6,1.95) E13(3.25,1.95) E14(3.9,1.95) E15(4.55,1.95) F1(-4.55,1.3) F2(-3.9,1.3) F3(-3.25,1.3) F4(-2.6,1.3) F6(-1.3,1.3) F7(-0.65,1.3) F8(0,1.3) F9(0.65,1.3) F10(1.3,1.3) F12(2.6,1.3) F13(3.25,1.3) F14(3.9,1.3) F15(4.55,1.3) G1(-4.55,0.65) G2(-3.9,0.65) G3(-3.25,0.65) G4(-2.6,0.65) G6(-1.3,0.65) G7(-0.65,0.65) G8(0,0.65) G9(0.65,0.65) G10(1.3,0.65) G12(2.6,0.65) G13(3.25,0.65) G14(3.9,0.65) G15(4.55,0.65) H1(-4.55,0) H2(-3.9,0) H3(-3.25,0) H4(-2.6,0) H6(-1.3,0) H7(-0.65,0) H8(0,0) H9(0.65,0) H10(1.3,0) H12(2.6,0) H13(3.25,0) H14(3.9,0) H15(4.55,0) J1(-4.55,-0.65) J2(-3.9,-0.65) J3(-3.25,-0.65) J4(-2.6,-0.65) J6(-1.3,-0.65) J7(-0.65,-0.65) J8(0,-0.65) J9(0.65,-0.65) J10(1.3,-0.65) J12(2.6,-0.65) J13(3.25,-0.65) J14(3.9,-0.65) J15(4.55,-0.65) K1(-4.55,-1.3) K2(-3.9,-1.3) K3(-3.25,-1.3) K4(-2.6,-1.3) K6(-1.3,-1.3) K7(-0.65,-1.3) K8(0,-1.3) K9(0.65,-1.3) K10(1.3,-1.3) K12(2.6,-1.3) K13(3.25,-1.3) K14(3.9,-1.3) K15(4.55,-1.3) L1(-4.55,-1.95) L2(-3.9,-1.95) L3(-3.25,-1.95) L4(-2.6,-1.95) L12(2.6,-1.95) L13(3.25,-1.95) L14(3.9,-1.95) L15(4.55,-1.95) M1(-4.55,-2.6) M2(-3.9,-2.6) M3(-3.25,-2.6) M4(-2.6,-2.6) M5(-1.95,-2.6) M6(-1.3,-2.6) M7(-0.65,-2.6) M8(0,-2.6) M9(0.65,-2.6) M10(1.3,-2.6) M11(1.95,-2.6) M12(2.6,-2.6) M13(3.25,-2.6) M14(3.9,-2.6) M15(4.55,-2.6) N1(-4.55,-3.25) N2(-3.9,-3.25) N3(-3.25,-3.25) N4(-2.6,-3.25) N5(-1.95,-3.25) N6(-1.3,-3.25) N7(-0.65,-3.25) N8(0,-3.25) N9(0.65,-3.25) N10(1.3,-3.25) N11(1.95,-3.25) N12(2.6,-3.25) N13(3.25,-3.25) N14(3.9,-3.25) N15(4.55,-3.25) P1(-4.55,-3.9) P2(-3.9,-3.9) P3(-3.25,-3.9) P4(-2.6,-3.9) P5(-1.95,-3.9) P6(-1.3,-3.9) P7(-0.65,-3.9) P8(0,-3.9) P9(0.65,-3.9) P10(1.3,-3.9) P11(1.95,-3.9) P12(2.6,-3.9) P13(3.25,-3.9) P14(3.9,-3.9) P15(4.55,-3.9) R1(-4.55,-4.55) R2(-3.9,-4.55) R3(-3.25,-4.55) R4(-2.6,-4.55) R5(-1.95,-4.55) R6(-1.3,-4.55) R7(-0.65,-4.55) R8(0,-4.55) R9(0.65,-4.55) R10(1.3,-4.55) R11(1.95,-4.55) R12(2.6,-4.55) R13(3.25,-4.55) R14(3.9,-4.55) R15(4.55,-4.55)
  silkscreen extent -5.22,-5.07 5.07,5.23, body extent -5.07,-5.07 5.07,5.07, height 0.61
ICC_UFQFPN28_4X4_P050 [mm] "MCD-02218"
  rect 0.3x0.3 smd mask+0.05: 1(-1.5,-2) 7(1.5,-2) 8(2,-1.5) 14(2,1.5) 15(1.5,2) 21(-1.5,2) 22(-2,1.5) 28(-2,-1.5)
  rect 0.3x0.55 smd mask+0.05: 2(-1,-1.875) 3(-0.5,-1.875) 4(0,-1.875) 5(0.5,-1.875) 6(1,-1.875) 16(1,1.875) 17(0.5,1.875) 18(0,1.875) 19(-0.5,1.875) 20(-1,1.875)
  rect 0.55x0.3 smd mask+0.05: 9(1.875,-1) 10(1.875,-0.5) 11(1.875,0) 12(1.875,0.5) 13(1.875,1) 23(-1.875,1) 24(-1.875,0.5) 25(-1.875,0) 26(-1.875,-0.5) 27(-1.875,-1)
  Top Layer region: -1.35,2.15 -1.35,1.65 -1.5,1.65 -1.65,1.8 -1.65,2.15
  Top Layer region: -2.15,1.35 -1.65,1.35 -1.65,1.5 -1.8,1.65 -2.15,1.65
  Top Layer region: -2.15,-1.35 -1.65,-1.35 -1.65,-1.5 -1.8,-1.65 -2.15,-1.65
  Top Layer region: -1.35,-2.15 -1.35,-1.65 -1.5,-1.65 -1.65,-1.8 -1.65,-2.15
  Top Layer region: 2.15,-1.35 1.65,-1.35 1.65,-1.5 1.8,-1.65 2.15,-1.65
  Top Layer region: 1.35,-2.15 1.35,-1.65 1.5,-1.65 1.65,-1.8 1.65,-2.15
  Top Layer region: 2.15,1.35 1.65,1.35 1.65,1.5 1.8,1.65 2.15,1.65
  Top Layer region: 1.35,2.15 1.35,1.65 1.5,1.65 1.65,1.8 1.65,2.15
  silkscreen extent -2,-2 2,2, body extent -2,-2 2,2, height 0.6
ICC_VFBGA49_3X3_P040 [mm] "MCD-02213"
  round 0.26 smd mask+0.03: A1(-1.2,1.2) A2(-0.8,1.2) A3(-0.4,1.2) A4(0,1.2) A5(0.4,1.2) A6(0.8,1.2) A7(1.2,1.2) B1(-1.2,0.8) B2(-0.8,0.8) B3(-0.4,0.8) B4(0,0.8) B5(0.4,0.8) B6(0.8,0.8) B7(1.2,0.8) C1(-1.2,0.4) C2(-0.8,0.4) C3(-0.4,0.4) C4(0,0.4) C5(0.4,0.4) C6(0.8,0.4) C7(1.2,0.4) D1(-1.2,0) D2(-0.8,0) D3(-0.4,0) D4(0,0) D5(0.4,0) D6(0.8,0) D7(1.2,0) E1(-1.2,-0.4) E2(-0.8,-0.4) E3(-0.4,-0.4) E4(0,-0.4) E5(0.4,-0.4) E6(0.8,-0.4) E7(1.2,-0.4) F1(-1.2,-0.8) F2(-0.8,-0.8) F3(-0.4,-0.8) F4(0,-0.8) F5(0.4,-0.8) F6(0.8,-0.8) F7(1.2,-0.8) G1(-1.2,-1.2) G2(-0.8,-1.2) G3(-0.4,-1.2) G4(0,-1.2) G5(0.4,-1.2) G6(0.8,-1.2) G7(1.2,-1.2)
  body extent -1.5,-1.5 1.5,1.5, height 1.01
ICC_VFBGA96_9x13_P080 [mm]
  round 0.4 smd mask+0.05: A1(-3.2,6) A2(-2.4,6) A3(-1.6,6) A7(1.6,6) A8(2.4,6) A9(3.2,6) B1(-3.2,5.2) B2(-2.4,5.2) B3(-1.6,5.2) B7(1.6,5.2) B8(2.4,5.2) B9(3.2,5.2) C1(-3.2,4.4) C2(-2.4,4.4) C3(-1.6,4.4) C7(1.6,4.4) C8(2.4,4.4) C9(3.2,4.4) D1(-3.2,3.6) D2(-2.4,3.6) D3(-1.6,3.6) D7(1.6,3.6) D8(2.4,3.6) D9(3.2,3.6) E1(-3.2,2.8) E2(-2.4,2.8) E3(-1.6,2.8) E7(1.6,2.8) E8(2.4,2.8) E9(3.2,2.8) F1(-3.2,2) F2(-2.4,2) F3(-1.6,2) F7(1.6,2) F8(2.4,2) F9(3.2,2) G1(-3.2,1.2) G2(-2.4,1.2) G3(-1.6,1.2) G7(1.6,1.2) G8(2.4,1.2) G9(3.2,1.2) H1(-3.2,0.4) H2(-2.4,0.4) H3(-1.6,0.4) H7(1.6,0.4) H8(2.4,0.4) H9(3.2,0.4) J1(-3.2,-0.4) J2(-2.4,-0.4) J3(-1.6,-0.4) J7(1.6,-0.4) J8(2.4,-0.4) J9(3.2,-0.4) K1(-3.2,-1.2) K2(-2.4,-1.2) K3(-1.6,-1.2) K7(1.6,-1.2) K8(2.4,-1.2) K9(3.2,-1.2) L1(-3.2,-2) L2(-2.4,-2) L3(-1.6,-2) L7(1.6,-2) L8(2.4,-2) L9(3.2,-2) M1(-3.2,-2.8) M2(-2.4,-2.8) M3(-1.6,-2.8) M7(1.6,-2.8) M8(2.4,-2.8) M9(3.2,-2.8) N1(-3.2,-3.6) N2(-2.4,-3.6) N3(-1.6,-3.6) N7(1.6,-3.6) N8(2.4,-3.6) N9(3.2,-3.6) P1(-3.2,-4.4) P2(-2.4,-4.4) P3(-1.6,-4.4) P7(1.6,-4.4) P8(2.4,-4.4) P9(3.2,-4.4) R1(-3.2,-5.2) R2(-2.4,-5.2) R3(-1.6,-5.2) R7(1.6,-5.2) R8(2.4,-5.2) R9(3.2,-5.2) T1(-3.2,-6) T2(-2.4,-6) T3(-1.6,-6) T7(1.6,-6) T8(2.4,-6) T9(3.2,-6)
  silkscreen extent -4.72,-6.55 4.55,6.73, body extent -4.55,-6.55 4.55,6.55, height 1
ICC_VFDFPN8-EPAD_3X3_P065 [mm] "MCD-02243"
  round 0.025 smd mask+0.05: 1(-0.975,-1.475) 2(-0.325,-1.475) 3(0.325,-1.475) 4(0.975,-1.475) 5(0.975,1.475) 6(0.325,1.475) 7(-0.325,1.475) 8(-0.975,1.475)
  rect 2.55x1.65 smd mask+0.05: 9(0,0)
  Top Layer region: -0.8,-1.2 -0.813,-1.133 -0.851,-1.076 -0.908,-1.038 -0.975,-1.025 -0.975,-1.025 -0.975,-1.025 -1.042,-1.038 -1.099,-1.076 -1.137,-1.133 -1.15,-1.2 -1.15,-1.2 -1.15,-1.75 -0.8,-1.75
  Top Layer region: -0.15,-1.2 -0.163,-1.133 -0.201,-1.076 -0.258,-1.038 -0.325,-1.025 -0.325,-1.025 -0.325,-1.025 -0.392,-1.038 -0.449,-1.076 -0.487,-1.133 -0.5,-1.2 -0.5,-1.2 -0.5,-1.75 -0.15,-1.75
  Top Layer region: 0.5,-1.2 0.487,-1.133 0.449,-1.076 0.392,-1.038 0.325,-1.025 0.325,-1.025 0.325,-1.025 0.258,-1.038 0.201,-1.076 0.163,-1.133 0.15,-1.2 0.15,-1.2 0.15,-1.75 0.5,-1.75
  Top Layer region: 1.15,1.2 1.137,1.133 1.099,1.076 1.042,1.038 0.975,1.025 0.975,1.025 0.975,1.025 0.908,1.038 0.851,1.076 0.813,1.133 0.8,1.2 0.8,1.2 0.8,1.75 1.15,1.75
  Top Layer region: 0.5,1.2 0.487,1.133 0.449,1.076 0.392,1.038 0.325,1.025 0.325,1.025 0.325,1.025 0.258,1.038 0.201,1.076 0.163,1.133 0.15,1.2 0.15,1.2 0.15,1.2 0.15,1.75 0.5,1.75
  Top Layer region: -0.8,1.2 -0.813,1.133 -0.851,1.076 -0.908,1.038 -0.975,1.025 -0.975,1.025 -0.975,1.025 -1.042,1.038 -1.099,1.076 -1.137,1.133 -1.15,1.2 -1.15,1.2 -1.15,1.75 -0.8,1.75
  Top Layer region: 1.15,-1.2 1.137,-1.133 1.099,-1.076 1.042,-1.038 0.975,-1.025 0.975,-1.025 0.908,-1.038 0.852,-1.076 0.814,-1.132 0.801,-1.199 0.801,-1.199 0.801,-1.2 0.8,-1.2 0.8,-1.75 1.15,-1.75
  Top Layer region: -0.15,1.2 -0.163,1.133 -0.201,1.076 -0.258,1.038 -0.325,1.025 -0.325,1.025 -0.392,1.038 -0.449,1.076 -0.487,1.133 -0.5,1.2 -0.5,1.2 -0.5,1.75 -0.15,1.75
  silkscreen extent -1.5,-1.5 1.5,1.5, body extent -1.5,-1.5 1.5,1.5, height 1
ICC_VFQFPN28-EPAD_4X4_P040 [mm]
  rect 0.65x0.2 smd mask+0.05: 1(-1.9,1.2) 2(-1.9,0.8) 3(-1.9,0.4) 4(-1.9,0) 5(-1.9,-0.4) 6(-1.9,-0.8) 7(-1.9,-1.2) 15(1.9,-1.2) 16(1.9,-0.8) 17(1.9,-0.4) 18(1.9,0) 19(1.9,0.4) 20(1.9,0.8) 21(1.9,1.2)
  rect 0.2x0.65 smd mask+0.05: 8(-1.2,-1.9) 9(-0.8,-1.9) 10(-0.4,-1.9) 11(0,-1.9) 12(0.4,-1.9) 13(0.8,-1.9) 14(1.2,-1.9) 22(1.2,1.9) 23(0.8,1.9) 24(0.4,1.9) 25(0,1.9) 26(-0.4,1.9) 27(-0.8,1.9) 28(-1.2,1.9)
  rect 2.7x2.7 smd mask+0.05: 29(0,0)
  body extent -2,-2 2,2, height 1.1
ICC_VQFN24-EPAD_4X4_P050 [mm]
  rrect50% 0.85x0.3 smd mask+0.05: 1(-1.95,1.25) 2(-1.95,0.75) 3(-1.95,0.25) 4(-1.95,-0.25) 5(-1.95,-0.75) 6(-1.95,-1.25) 13(1.95,-1.25) 14(1.95,-0.75) 15(1.95,-0.25) 16(1.95,0.25) 17(1.95,0.75) 18(1.95,1.25)
  rrect50% 0.3x0.85 smd mask+0.05: 7(-1.25,-1.95) 8(-0.75,-1.95) 9(-0.25,-1.95) 10(0.25,-1.95) 11(0.75,-1.95) 12(1.25,-1.95) 19(1.25,1.95) 20(0.75,1.95) 21(0.25,1.95) 22(-0.25,1.95) 23(-0.75,1.95) 24(-1.25,1.95)
  rect 2.6x2.6 smd paste-10 mask+0.05: EP(0,0)
  body extent -2.05,-2.05 2.05,2.05, height 1.1
ICC_VSSOP8_DCU_R-PDSO-G8_2X2P30_P050 [mm]
  rect 0.3x0.8 smd mask+0.05: 1(-0.75,-1.55) 2(-0.25,-1.55) 3(0.25,-1.55) 4(0.75,-1.55) 5(0.75,1.55) 6(0.25,1.55) 7(-0.25,1.55) 8(-0.75,1.55)
  silkscreen extent -1.05,-1.2 1.05,1.2, body extent -1.05,-1.62 1.05,1.62, height 0.9
IND_0402_MURATA_LQW15AN2N4C00X [mm]
  rect 0.65x0.9 smd mask+0.05: 1(-0.475,0) 2(0.475,0)
  silkscreen extent -0.05,-0.35 0.05,0.35, body extent -0.55,-0.35 0.55,0.35, height 0.6
IND_2016_SAMSUNG_CIGT2016 [mm] "MCD-04058"
  rect 0.8x1.8 smd mask+0.05: 1(-0.8,0) 2(0.8,0)
  silkscreen extent -0.28,-0.87 0.28,0.87, body extent -1.07,-0.87 1.08,0.87, height 1
IND_2520_TOKO_DFE252012P [mm]
  rect 0.8x2 smd mask+0.05: 1(-1,0) 2(1,0)
  silkscreen extent -1.35,-1.12 1.35,1.12, body extent -1.35,-1.1 1.35,1.1, height 2
L0603 [mm]
  rect 0.8x0.95 smd mask+0.05: 1(-0.8,0) 2(0.8,0)
  Top Layer keep-out region: -0.4,-0.474 0.4,-0.474 0.4,0.476 -0.4,0.476
  body extent -0.87,-0.47 0.87,0.47, height 0.95
L1210_LQH [mm]
  rect 1.7x3.1 smd mask+0.05: 1(-1.1,0) 2(1.1,0)
  silkscreen extent -2.05,-1.65 2.05,1.65, body extent -1.75,-1.35 1.75,1.35, height 2
LCD_DRAWING_ROCKTEK_RK043FN78H-CT661C [mm] "MCD-02422"
  silkscreen extent -52.62,-45 52.88,22.2, body extent -52.62,-45 52.88,22.2, height 4.53
LED_0603_GREEN [mm]
  rect 0.8x0.8 smd mask+0.05: 1(-0.75,0) 2(0.75,0)
  Top Layer keep-out region: -0.35,0.4 0.35,0.4 0.35,-0.4 -0.35,-0.4
  body extent -0.8,-0.4 0.8,0.4, height 0.6
LED_0603_ORANGE_H0P4 [mm]
  rect 0.8x0.8 smd mask+0.05: 1(-0.75,0) 2(0.75,0)
  Top Layer keep-out region: -0.35,0.4 0.35,0.4 0.35,-0.4 -0.35,-0.4
  body extent -0.8,-0.4 0.79,0.4, height 0.4
LED_0603_RED [mm]
  rect 0.8x0.8 smd mask+0.05: 1(-0.75,0) 2(0.75,0)
  Top Layer keep-out region: -0.35,0.4 0.35,0.4 0.35,-0.4 -0.35,-0.4
  body extent -0.8,-0.4 0.8,0.4, height 0.6
LED_0603_SMD-B_BLUE_H0P4 [mm]
  rect 0.6x1 smd mask+0.05: 1(-0.65,0) 2(0.65,0)
  Top Layer keep-out region: -0.35,0.5 0.35,0.5 0.35,-0.5 -0.35,-0.5
  body extent -0.85,-0.45 0.85,0.45, height 0.5
LED_BI-GR_CMD67-22 [mm] "MCD-02629"
  rect 1.1x1.5 smd mask+0.05: 1(-0.75,-1.5) 2(0.75,-1.5) 3(-0.75,1.5) 4(0.75,1.5)
  silkscreen extent -1.5,-1.7 1.7,1.9, body extent -1.5,-1.85 1.5,1.85, height 2.1
MOD_WLAN-BT_MURATA_LBEE5KL1DX-883 [mm]
  rect 0.25x0.5 smd mask+0.05: 1(-2.25,-2.025) 2(-1.8,-2.025) 3(-1.35,-2.025) 4(-0.9,-2.025) 5(-0.45,-2.025) 6(0,-2.025) 7(0.45,-2.025) 8(0.9,-2.025) 9(1.35,-2.025) 10(1.8,-2.025) 11(2.25,-2.025) 22(2.25,2.025) 23(1.8,2.025) 24(1.35,2.025) 25(0.9,2.025) 26(0.45,2.025) 27(0,2.025) 28(-0.45,2.025) 29(-0.9,2.025) 30(-1.35,2.025) 31(-1.8,2.025) 32(-2.25,2.025)
  rect 0.5x0.375 smd mask+0.05: 12(2.925,-2.087) 21(2.925,2.087) 33(-2.925,2.087) 42(-2.925,-2.087)
  rect 0.5x0.25 smd mask+0.05: 13(2.925,-1.575) 14(2.925,-1.125) 15(2.925,-0.675) 16(2.925,-0.225) 17(2.925,0.225) 18(2.925,0.675) 19(2.925,1.125) 20(2.925,1.575) 34(-2.925,1.575) 35(-2.925,1.125) 36(-2.925,0.675) 37(-2.925,0.225) 38(-2.925,-0.225) 39(-2.925,-0.675) 40(-2.925,-1.125) 41(-2.925,-1.575)
  rect 1x1 smd mask+0.05: 43(-1,-0.75) 44(1,-0.75) 45(-1,0.75) 46(1,0.75)
  silkscreen extent -3.57,-2.68 3.57,2.68, body extent -3.57,-2.68 3.57,2.68, height 1.11
MOS_SOT23 [mm]
  rect 1x1.4 smd mask+0.05: 1(-0.95,-1.1) 2(0.95,-1.1) 3(0,1.1)
  silkscreen extent -1.63,-0.82 1.63,0.82, body extent -1.56,-1.25 1.56,1.25, height 1.1
OSC_NDK_NZ2520SB_4P [mm]
  rect 1x1 smd mask+0.05: 1(-0.825,-0.625) 2(0.825,-0.625) 3(0.825,0.625) 4(-0.825,0.625)
  silkscreen extent -1.43,-1.22 1.2,1.05, body extent -1.3,-1.05 1.3,1.05, height 0.91
PowerFLAT_5x6 [mm] "MCD-02152"
  rect 0.65x1.25 smd mask+0.05: 1(1.905,2.675) 2(0.635,2.675) 3(-0.635,2.675) 4(-1.905,2.675) 5(-1.905,-2.675) 6(-0.635,-2.675) 7(0.635,-2.675) 8(1.905,-2.675)
  Top Layer region: -0.2,-3.3 -0.95,-3.3 -0.95,-2.75 -1.575,-2.75 -1.575,-3.3 -2.3,-3.3 -2.3,-2.3 -2.7,-2.3 -2.7,-1.5 -2.3,-1.5 -2.3,0.15 -2.7,0.15 -2.7,0.975 -2.3,0.975 -2.3,1.15 -0.2,1.15
  Top Layer region: 0.2,-3.3 0.95,-3.3 0.95,-2.75 1.575,-2.75 1.575,-3.3 2.3,-3.3 2.3,-2.3 2.7,-2.3 2.7,-1.5 2.3,-1.5 2.3,0.15 2.7,0.15 2.7,0.975 2.3,0.975 2.3,1.15 0.2,1.15
  silkscreen extent -2.5,-3 2.5,3, body extent -2.6,-3.08 2.6,3.07, height 1
R0402#1 [mm]
  rect 0.51x0.7 smd mask+0.05: 1(-0.45,0) 2(0.45,0)
  Top Layer keep-out region: -0.175,-0.35 0.175,-0.35 0.175,0.35 -0.175,0.35
  body extent -0.52,-0.3 0.52,0.3, height 0.4
R0402#2 [mm]
  rect 0.51x0.7 smd mask+0.05: 1(-0.45,0) 2(0.45,0)
  body extent -0.52,-0.3 0.52,0.3, height 0.4
R0603#1 [mm]
  rect 0.64x1 smd mask+0.05: 1(-0.7,0) 2(0.7,0)
  Top Layer keep-out region: -0.375,-0.5 0.375,-0.5 0.375,0.5 -0.375,0.5
  body extent -0.9,-0.5 0.9,0.5, height 0.56
R0603#2 [mm]
  rect 0.64x1 smd mask+0.05: 1(-0.7,0) 2(0.7,0)
  silkscreen extent -1.05,-0.58 1.05,0.58, body extent -0.9,-0.5 0.9,0.5, height 0.56
R0603_H070 [mm] "MCD-03129"
  rect 0.7x1 smd mask+0.05: 1(-0.8,0) 2(0.8,0)
  body extent -0.85,-0.45 0.85,0.45, height 0.7
REG_SOT23-5L [mm]
  rect 0.6x1.3 smd mask+0.05: 1(-0.95,-1.1) 2(0,-1.1) 3(0.95,-1.1) 4(0.95,1.1) 5(-0.95,1.1)
  silkscreen extent -1.6,-0.95 1.6,0.97, body extent -1.52,-1.25 1.52,1.25, height 1.1
STICKER_BOARD_25X9 [mm] "Sticker to mention board CPN code"
  silkscreen extent -12.5,-4.5 12.5,4.5
STICKER_PRODUCT_25X9 [mm] "Sticker to mention board CPN code"
  silkscreen extent -12.5,-4.5 12.5,4.5
SWI_GRAYHILL-INC_76SB04ST [mm] "MCD-02256"
  rect 1.5x1.5 hole 0.9 mask+0.05: 1(-3.75,-3.81)
  round 1.5 hole 0.9 mask+0.05: 2(-1.25,-3.81) 3(1.25,-3.81) 4(3.75,-3.81) 5(3.75,3.81) 6(1.25,3.81) 7(-1.25,3.81) 8(-3.75,3.81)
  silkscreen extent -6.1,-4.82 6.1,4.82, body extent -6.1,-4.83 6.1,4.82, height 6.9
SWI_KNITTER_TSS644S [mm] "MCD-02417"
  rect 1.55x1.3 smd mask+0.05: 1(-3.975,2.25) 2(3.975,2.25) 3(-3.975,-2.25) 4(3.975,-2.25)
  silkscreen extent -3.1,-3.1 3.1,3.1, body extent -4.5,-3.1 4.5,3.1, height 7.3
TP_SMD_1MM#1 [mm]
  round 1 smd paste-10 mask+0.05: 1(0,0)
  silkscreen extent -0.7,-0.7 0.7,0.7
TP_SMD_1MM#2 [mm]
  round 1 smd paste-10 mask+0.05: 1(-0.05,0)
  silkscreen extent -0.7,-0.7 0.7,0.7
TP_SMD_1MM#3 [mm]
  round 1 smd paste-10 mask+0.05: 1(0,0.05)
  silkscreen extent -0.7,-0.7 0.7,0.7
TP_SMD_1MM#4 [mm]
  round 1 smd paste-10 mask+0.05: 1(0,-0.025)
  silkscreen extent -0.7,-0.7 0.7,0.7
TP_SMD_2MM [mm]
  round 2 smd paste-10 mask+0.05: 1(0,0)
  silkscreen extent -1.2,-1.2 1.2,1.2

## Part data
B1 B2 B4 B5: library part MCD-02417, "Push Button, NO, 0.05A, 12V, 2.6N, SMD, 9.0x6.2mm, T=7.3mm, changeable caps KTSC-6xx", Manufacturer=KNITTER-SWITCH, Manufacturer_HQ_COO=Unknown, Manufacturer_Part_Number=TSS644S, Package=9.0x6.2mm
B3: library part MCD-02417, "Push Button, NO, 0.05A, 12V, Salmon", Manufacturer=KNITTER-SWITCH, Manufacturer_HQ_COO=Unknown, Manufacturer_Part_Number=TSS644S, Package=9.0x6.2mm
C1 C2 C3 C4: library part MCD-00200, "Capacitor, MLCC, 12pF, 50V, NPO, +/-5%, 0402, T=0.5mm", Manufacturer=YAGEO, Manufacturer_Part_Number=CC0402JRNPO9BN120, Package=0402
C5 C10 C17 C23 C24 C40 C92 C171 C173 C174 C176 C177 C182 C183 C185 C186 C187 C188 C189 C190 C191 C194 C195 C196 C197 C198 C199 C200 C201 C202 C203 C205 C207 C208 C209 C212 C213 C214 C215 C219: library part MCD-02377, "Capacitor, MLCC, 1uF, 6.3V, X5R, +/-20%, 0201, T=0,3mm", Manufacturer=MURATA, Manufacturer_Part_Number=GRM033R60J105MEA2, Package=0201
C6 C36 C43: library part MCD-00095, "Capacitor, MLCC, 1uF, 25V, X5R, +/-10%, 0402, T=0.5mm", Manufacturer=MURATA, Manufacturer_Part_Number=GRM155R61E105KA12, Package=0402
C7 C8 C9 C11 C12 C13 C15 C16 C22 C25 C26 C28 C30 C31 C32 C33 C35 C37 C41 C44 C46 C47 C48 C49 C53 C57 C58 C59 C61 C62 C63 C65 C67 C68 C69 C70 C71 C74 C75 C76 C77 C78 C79 C80 C81 C82 C83 C85 C89 C94 C102 C104 C105 C106 C107 C108 C118 C119 C121 C135 C138 C150 C152 C153 C154 C157 C158 C163 C165 C169 C170 C178 C179 C180 C181 C210 C218 C220 C226 C227: library part MCD-00006, "Capacitor, MLCC, 100nF, 16V, X7R, +/-10%, 0402, T=0.5mm", Manufacturer=YAGEO, Manufacturer_Part_Number=CC0402KRX7R7BB104, Package=0402
C14 C34 C54 C55 C117 C140 C151 C156 C223 C228: library part MCD-02198, "Capacitor, MLCC, 10nF, 50V, X7R, +/-10%, 0402, T=0.5mm", Manufacturer=YAGEO, Manufacturer_Part_Number=CC0402KRX7R9BB103, Package=0402
C18 C60 C64 C73 C216 C217: library part MCD-02235, "Capacitor, MLCC, 2.2uF, 10V, X5R,+/-10%, 0201, T=0.5mm", Manufacturer=MURATA, Manufacturer_Part_Number=GRM033R61A225KE47, Package=0201
C19 C27 C29 C39 C91 C112 C115 C123 C125 C134 C167 C172: library part MCD-00099, "Capacitor, MLCC, 10uF, 10V, X5R, +/-10%, 0603, T=0.8mm", Manufacturer=MURATA, Manufacturer_Part_Number=GRM188R61A106KE69, Package=0603
C20 C21 C42 C50 C109 C139 C168: library part MCD-01356, "Capacitor, MLCC, 4.7uF, 6V3, X5R, +/-20%, 0402, T=0.5mm", Manufacturer=MURATA, Manufacturer_Part_Number=GRM155R60J475ME47, Package=0402
C38 C90 C147 C148: library part MCD-00724, "Capacitor, MLCC, 470pF, 50V, NPO, +/-5%, 0402, T=0.5mm", Manufacturer=YAGEO, Manufacturer_Part_Number=CC0402JRNPO9BN471, Package=0402
C45 C51: library part MCD-00013, "Capacitor, MLCC, 4.7uF, 50V, X7R, +/-10%, 1206, T=1.27mm", Manufacturer=AVX, Manufacturer_Part_Number=12065C475KAT2A, Package=1206
C52 C149: library part MCD-01099, "Capacitor, MLCC, 100nF, 50V, X7R, +/-10%, 0603, T=0.8mm", Manufacturer=YAGEO, Manufacturer_Part_Number=CC0603KRX7R9BB104, Package=0603
C56: library part MCD-00277, "Capacitor, MLCC, 33pF, 50V, NPO,+/-5%, 0402, T=0.5mm", Manufacturer=YAGEO, Manufacturer_Part_Number=CC0402JRNPO9BN330, Package=0402
C66 C72 C110 C113 C114 C116 C124 C126 C127 C128 C129 C133: library part MCD-00100, "Capacitor, MLCC, 22uF, 6V3, X5R, +/-20%, 0603, T=0.8mm", Manufacturer=MURATA, Manufacturer_Part_Number=GRM188R60J226MEA0, Package=0603
C84 C221 C229: library part MCD-00205, "Capacitor, MLCC, 100pF, 50V, NPO, +/-5%, 0402, T=0.5mm", Manufacturer=YAGEO, Manufacturer_Part_Number=CC0402JRNPO9BN101, Package=0402
C86: library part MCD-00198, "Capacitor, MLCC, 1nF, 16V, X7R, +/-10%, 0402, T=0.5mm", Manufacturer=YAGEO, Manufacturer_Part_Number=CC0402KRX7R7BB102, Package=0402
C87: library part MCD-01995, "Capacitor, MLCC, 22pF, 50V, C0G, +/-5%, 0402, T=0.5mm", Manufacturer=TDK, Manufacturer_Part_Number=C1005NP01H220J050BA, Package=0402
C88 C93 C95 C96 C98 C103 C159 C164: library part MCD-00674, "Capacitor, MLCC, 6.8pF, 50V, NPO, +/-0.25pF, 0402, T=0.5mm", Manufacturer=YAGEO, Manufacturer_Part_Number=CC0402CRNPO9BN6R8, Package=0402
C97 C101 C122 C131 C166: library part MCD-00095, "Capacitor, MLCC, 1uF, 25V, X5R, 10%, 0402, T=0.5mm", Manufacturer=MURATA, Manufacturer_Part_Number=GRM155R61E105KA12, Package=0402
C99 C100 C111 C120 C142 C144: library part MCD-01356, "Capacitor, MLCC, 4.7uF, 6V3, X5R, 20%, 0402, T=0.5mm", Manufacturer=MURATA, Manufacturer_Part_Number=GRM155R60J475ME47, Package=0402
C130: library part MCD-02263, "Capacitor, MLCC, 47uF, 25V, X5R, 20%, 1206, T=1.6mm", Manufacturer=MURATA, Manufacturer_Part_Number=GRM31CR61E476ME44, Package=C1206
C136 C137 C162 C224 C225: library part MCD-00104, "Capacitor, MLCC, 220uF, 6V3, X5R, +/-20%, 1206, T=1.6mm", Manufacturer=MURATA, Manufacturer_Part_Number=GRM31CR60J227ME11, Package=1206
C155: library part MCD-01481, "Capacitor, MLCC, 390pF, 50V, C0G/NP0, +/-5%, 0402, T=0.5mm", Manufacturer=YAGEO, Manufacturer_Part_Number=CC0402JRNPO9BN391, Package=0402
C160: library part MCD-02372, "Capacitor, MLCC, 2.2uF, 25V, X7R, +/-10%, 0805, T=1,25mm", Manufacturer=MURATA, Manufacturer_Part_Number=GRM21BR71E225KE11, Package=0805
C161: library part MCD-00205, "Capacitor, MLCC, 100pF, 50V, C0G/NP0, +/-5%, 0402, T=0.5mm", Manufacturer=YAGEO, Manufacturer_Part_Number=CC0402JRNPO9BN101, Package=0402
C175 C184 C192 C193 C204 C206 C211: library part MCD-01729, "Capacitor, MLCC, 1nF, 25V, X7R,+/-5%, 0201,T=0.3mm", Manufacturer=MURATA, Manufacturer_Part_Number=GRM033R71E102JA01, Package=0201
C222: library part MCD-02378, "Capacitor, MLCC, 10uF, 50V, X7R, +/-10%, 1210, T=2.5mm", Manufacturer=TDK, Manufacturer_Part_Number=C3225X7R1H106K250AC, Package=1210
CN1: library part MCD-02225, "Socket_FFC/FPC, 15pins, 1mm ,VR, SMD, T=7.7mm", Manufacturer="TE CONNECTIVITY", Manufacturer_Part_Number=1-1734248-5
CN3: library part MCD-00653, "Connector_uSD Card, Top Mnt Push-Push", Manufacturer=ATOM
CN4 CN15: library part MCD-02475, "connector_RJ45, 10/100 Ethernet integrated MAG with integrate Green and Yellow LED, T= 13.61mm", Manufacturer=PENGHUI, Manufacturer_Part_Number=RMT-119A-12F6-GY-02
CN5 CN6: library part MCD-00109, "USB_Dual-TypeA, Receptacle, 8pins, 2.5mm, RA, TH, T= 15.5mm", Manufacturer=CONEXCON, Manufacturer_Part_Number=5600-3081
CN7 CN12: library part MCD-02421, "USB_TypeC, 24 pins, RA, SMD, T=3.71mm (USB Certified 3.1)", Manufacturer=MOLEX, Manufacturer_Part_Number=2012670005
CN8: library part MCD-00302, "Header, 20x2, 2.54mm, VR, TH, T=5.84mm/2.54mm", Manufacturer=SAMTEC, Manufacturer_Part_Number=TSW-120-07-G-D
